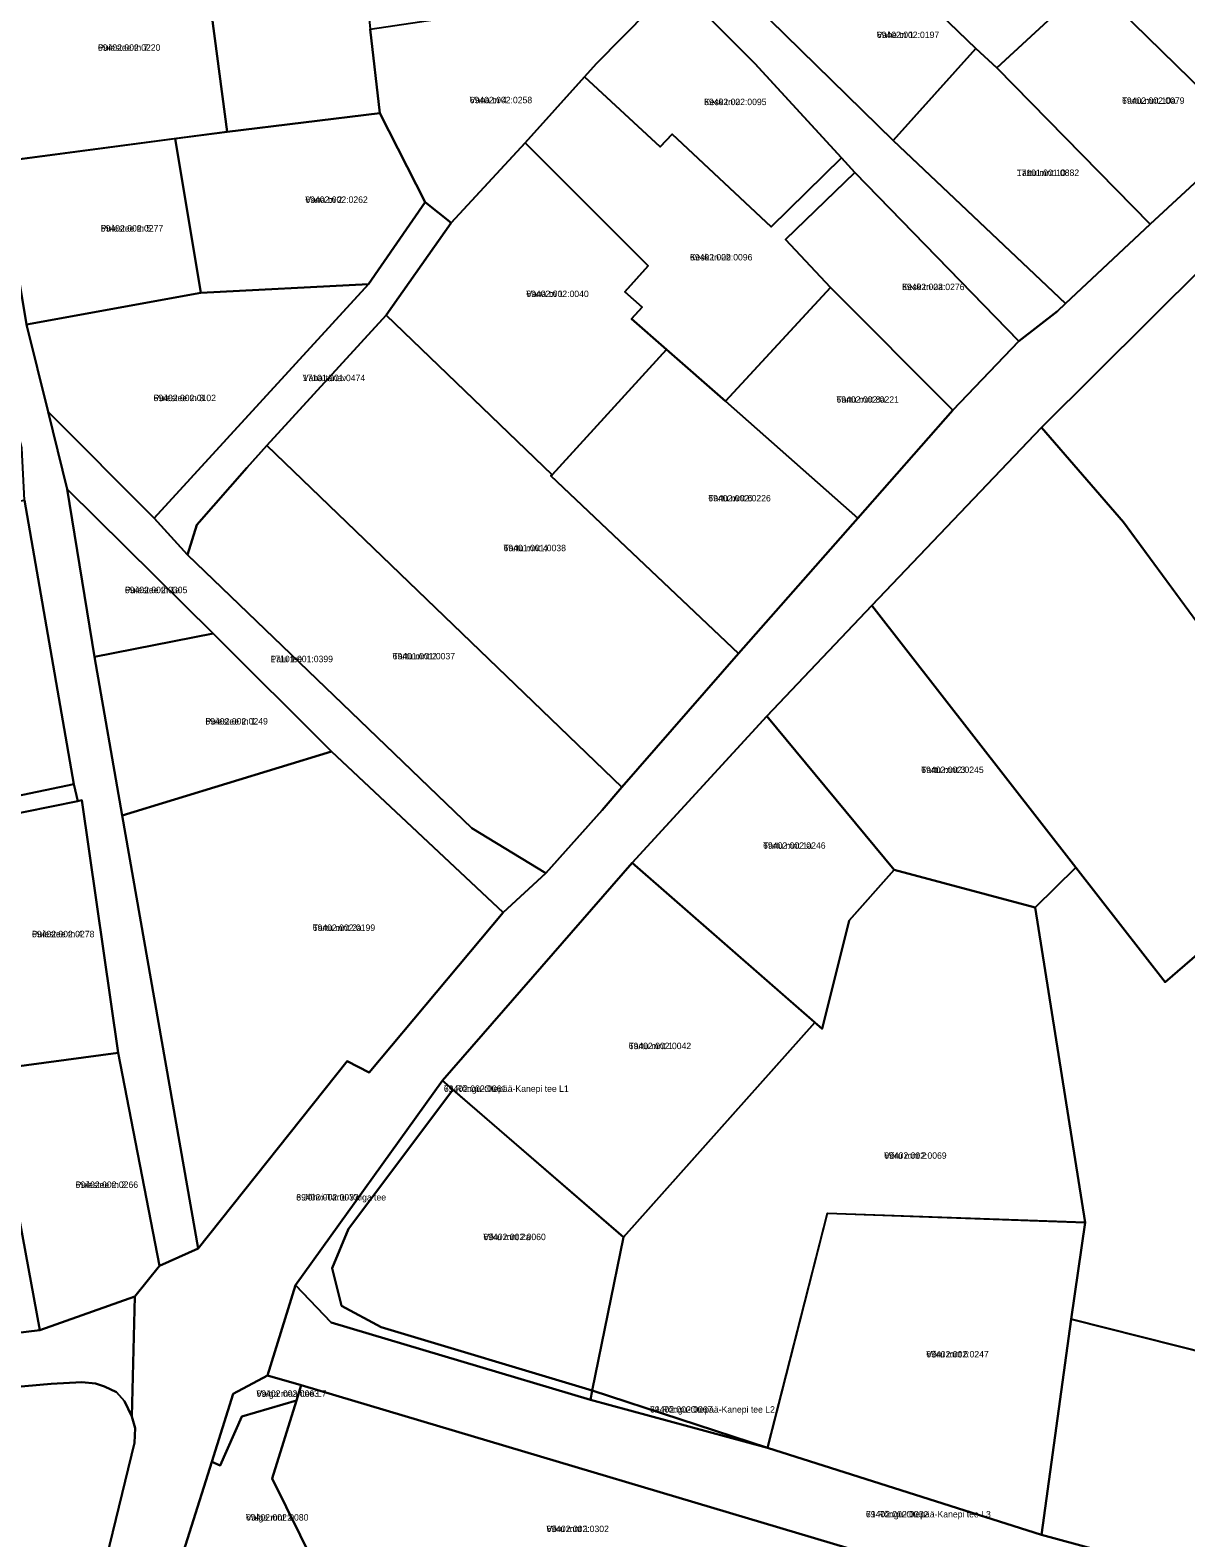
# Model space of a CAD drawing. Extents: x 621116 to 647354, y 6433782 to 6479868.
# Drawn here: x 632315.8 to 632584.2, y 6446793.4 to 6447143.7 of the extents above; entities that cross this region are included whole.
import ezdxf

# ---------------------------------------------------------------- set-up
doc = ezdxf.new("R2010")
doc.units = 0
for name, color, linetype in [('L_AADRESS', 7, 'Continuous'), ('PIIR', 7, 'Continuous'), ('TUNNUS', 7, 'Continuous')]:
    doc.layers.add(name, color=color, linetype=linetype)

msp = doc.modelspace()

# ---------------------------------------------------------------- linework, layer by layer
at = {"layer": 'PIIR'}
for points in [[(632883.55, 6447433.55), (632823.56, 6447364.54), (632765.83, 6447294.39), (632710.64, 6447218.39), (632706.33, 6447212.09), (632679.44, 6447177.2), (632680.2, 6447176.14), (632678.45, 6447175.07), (632645.86, 6447142.95), (632634.81, 6447132.1), (632588.47, 6447088.99), (632550.7, 6447051.42), (632511.3, 6447010.02), (632486.88, 6446984.32), (632455.65, 6446950.25), (632411.59, 6446899.66), (632377.44, 6446852.14), (632370.98, 6446831.17), (632362.97, 6446826.87), (632358.02, 6446811.05), (632347.63, 6446778.24)], [(633018.53, 6446892.34), (632855.22, 6446826.42), (632731.22, 6446817.27), (632630.88, 6446825.72), (632557.57, 6446844.2), (632560.82, 6446866.69), (632549.2, 6446939.86), (632558.62, 6446949.17), (632579.41, 6446922.53), (632647.93, 6446981.82), (632724.87, 6447048.64), (632767.82, 6447085.82), (632732.74, 6447116.24), (632780.64, 6447156.88), (632786.41, 6447163.78), (632792.83, 6447158.42), (632824.27, 6447148.02), (632854.81, 6447243.77), (632865.67, 6447258.13), (632870.09, 6447255.09)], [(632329.9, 6446773.82), (632340.08, 6446815.51), (632340.23, 6446818.86), (632339.46, 6446821.58), (632340.12, 6446849.46), (632345.88, 6446856.63), (632354.81, 6446860.66), (632389.48, 6446904.16), (632394.54, 6446901.51), (632425.68, 6446938.69), (632435.55, 6446947.84), (632448.65, 6446962.5), (632453.23, 6446967.82), (632480.34, 6446998.92), (632508.01, 6447030.37), (632530.09, 6447055.45), (632545.41, 6447071.48), (632554.37, 6447078.44), (632556.25, 6447080.21), (632575.88, 6447098.64), (632598.45, 6447119.53), (632620.08, 6447139.91), (632643.5, 6447161.29)], [(632300.82, 6447156.82), (632308.66, 6447113.17), (632315, 6447075.35), (632320.05, 6447055.08), (632324.42, 6447037.08), (632330.74, 6446998.15), (632337.2, 6446961.26), (632354.81, 6446860.66), (632345.88, 6446856.63), (632336.25, 6446906.14), (632327.85, 6446964.8), (632326.89, 6446964.62), (632325.97, 6446968.56), (632314.49, 6447034.52), (632313.86, 6447046.59), (632307.16, 6447073.73), (632300.78, 6447111.8), (632292.9, 6447155.68)], [(632487.56, 6447146.18), (632516.2, 6447118.12), (632556.25, 6447080.21), (632554.37, 6447078.44), (632545.41, 6447071.48), (632507.34, 6447110.67), (632504.26, 6447114.06), (632484.13, 6447135.98), (632465.58, 6447154.56)], [(632291.35, 6446838.41), (632318.09, 6446841.7), (632340.12, 6446849.46), (632339.46, 6446821.58), (632337.72, 6446825.15), (632335.87, 6446827.25), (632333.06, 6446828.6), (632331.02, 6446829.25), (632327.8, 6446829.55), (632320.73, 6446829.18), (632304.93, 6446827.8)]]:
    msp.add_lwpolyline(points, dxfattribs=at)
for points in [[(632508.36, 6447165.7), (632531.28, 6447186.21), (632562.08, 6447155.09), (632540.32, 6447135.02), (632535.43, 6447139.51)], [(632598.45, 6447119.53), (632562.08, 6447155.09), (632584.6, 6447175.85), (632620.08, 6447139.91)], [(632355.69, 6447164.73), (632392.41, 6447168.11), (632394.8, 6447144), (632397.04, 6447124.48), (632361.61, 6447120.15)], [(632516.2, 6447118.12), (632487.56, 6447146.18), (632508.36, 6447165.7), (632535.43, 6447139.51)], [(632355.69, 6447164.73), (632361.61, 6447120.15), (632308.66, 6447113.17), (632300.82, 6447156.82)], [(632598.45, 6447119.53), (632575.88, 6447098.64), (632540.32, 6447135.02), (632562.08, 6447155.09)], [(632447.32, 6447135.96), (632444.54, 6447132.89), (632430.75, 6447117.57), (632413.61, 6447098.97), (632407.57, 6447103.74), (632397.04, 6447124.48), (632394.8, 6447144), (632465.58, 6447154.56)], [(632504.26, 6447114.06), (632487.89, 6447098.08), (632464.89, 6447119.55), (632462.13, 6447116.65), (632444.54, 6447132.89), (632447.32, 6447135.96), (632465.58, 6447154.56), (632484.13, 6447135.98)], [(632516.2, 6447118.12), (632535.43, 6447139.51), (632540.32, 6447135.02), (632575.88, 6447098.64), (632556.25, 6447080.21)], [(632501.71, 6447083.97), (632477.32, 6447057.54), (632463.61, 6447069.56), (632455.47, 6447076.69), (632457.95, 6447079.4), (632453.91, 6447082.95), (632459.34, 6447088.95), (632430.75, 6447117.57), (632444.54, 6447132.89), (632462.13, 6447116.65), (632464.89, 6447119.55), (632487.89, 6447098.08), (632504.26, 6447114.06), (632507.34, 6447110.67), (632491.2, 6447095.08)], [(632394.39, 6447084.73), (632355.47, 6447082.74), (632349.47, 6447118.55), (632361.61, 6447120.15), (632397.04, 6447124.48), (632407.57, 6447103.74)], [(632349.47, 6447118.55), (632355.47, 6447082.74), (632315, 6447075.35), (632308.66, 6447113.17)], [(632430.75, 6447117.57), (632459.34, 6447088.95), (632453.91, 6447082.95), (632457.95, 6447079.4), (632455.47, 6447076.69), (632463.61, 6447069.56), (632437.02, 6447040.42), (632398.47, 6447077.52), (632413.61, 6447098.97)], [(632507.34, 6447110.67), (632545.41, 6447071.48), (632530.09, 6447055.45), (632501.71, 6447083.97), (632491.2, 6447095.08)], [(632344.64, 6447030.36), (632394.39, 6447084.73), (632407.57, 6447103.74), (632413.61, 6447098.97), (632398.47, 6447077.52), (632370.81, 6447047.22), (632366.12, 6447042.04), (632354.52, 6447028.81), (632352.33, 6447021.81)], [(632550.7, 6447051.42), (632588.47, 6447088.99), (632641.79, 6447032.42), (632621.77, 6447012.3), (632598.99, 6446989.55), (632569.7, 6447029.45)], [(632315, 6447075.35), (632355.47, 6447082.74), (632394.39, 6447084.73), (632344.64, 6447030.36), (632320.05, 6447055.08)], [(632501.71, 6447083.97), (632530.09, 6447055.45), (632508.01, 6447030.37), (632477.32, 6447057.54)], [(632436.72, 6447040.15), (632480.34, 6446998.92), (632453.23, 6446967.82), (632370.81, 6447047.22), (632398.47, 6447077.52), (632437.02, 6447040.42)], [(632463.61, 6447069.56), (632477.32, 6447057.54), (632508.01, 6447030.37), (632480.34, 6446998.92), (632436.72, 6447040.15), (632437.02, 6447040.42)], [(632320.05, 6447055.08), (632344.64, 6447030.36), (632352.33, 6447021.81), (632418.43, 6446958.33), (632435.55, 6446947.84), (632425.68, 6446938.69), (632385.82, 6446976.15), (632358.33, 6447003.54), (632324.42, 6447037.08)], [(632558.62, 6446949.17), (632511.3, 6447010.02), (632550.7, 6447051.42), (632569.7, 6447029.45), (632599.07, 6446989.55), (632621.77, 6447012.3), (632647.93, 6446981.82), (632579.41, 6446922.53)], [(632370.81, 6447047.22), (632453.23, 6446967.82), (632448.65, 6446962.5), (632435.55, 6446947.84), (632418.43, 6446958.33), (632352.33, 6447021.81), (632354.52, 6447028.81), (632366.12, 6447042.04)], [(632330.74, 6446998.15), (632324.42, 6447037.08), (632358.33, 6447003.54)], [(632314.49, 6447034.52), (632325.97, 6446968.56), (632268.52, 6446956.57), (632264.6, 6446987.12), (632259.6, 6447024.62)], [(632516.43, 6446948.67), (632486.88, 6446984.32), (632511.3, 6447010.02), (632558.62, 6446949.17), (632549.2, 6446939.86)], [(632337.2, 6446961.26), (632330.74, 6446998.15), (632358.33, 6447003.54), (632385.82, 6446976.15)], [(632499.72, 6446911.67), (632455.65, 6446950.25), (632486.88, 6446984.32), (632516.43, 6446948.67), (632505.98, 6446936.83)], [(632354.81, 6446860.66), (632337.2, 6446961.26), (632385.82, 6446976.15), (632425.68, 6446938.69), (632394.54, 6446901.51), (632389.48, 6446904.16)], [(632326.89, 6446964.62), (632296.26, 6446958.42), (632307.29, 6446899.81), (632277.79, 6446894.25), (632277.21, 6446897.8), (632272.99, 6446920.18), (632268.52, 6446956.57), (632325.97, 6446968.56)], [(632306.89, 6446902.19), (632296.26, 6446958.42), (632326.89, 6446964.62), (632327.85, 6446964.8), (632336.25, 6446906.14)], [(632498.05, 6446913.15), (632453.64, 6446863.31), (632411.59, 6446899.66), (632455.65, 6446950.25)], [(632516.43, 6446948.67), (632549.2, 6446939.86), (632560.82, 6446866.69), (632500.9, 6446868.8), (632487.04, 6446814.31), (632446.36, 6446827.67), (632453.64, 6446863.31), (632498.05, 6446913.15), (632499.72, 6446911.67), (632505.98, 6446936.83)], [(632306.89, 6446902.19), (632336.25, 6446906.14), (632345.88, 6446856.63), (632340.12, 6446849.46), (632318.09, 6446841.7), (632307.29, 6446899.81)], [(632318.09, 6446841.7), (632291.35, 6446838.41), (632275.32, 6446841.91), (632250, 6446856.81), (632216.84, 6446883.42), (632277.21, 6446897.8), (632277.79, 6446894.25), (632307.29, 6446899.81)], [(632411.59, 6446899.66), (632414.01, 6446897.51), (632389.74, 6446865.21), (632385.97, 6446856.11), (632388.12, 6446847.29), (632397.37, 6446842.35), (632446.36, 6446827.67), (632445.92, 6446825.51), (632385.73, 6446843.47), (632377.44, 6446852.14)], [(632414.01, 6446897.51), (632453.64, 6446863.31), (632446.36, 6446827.67), (632397.37, 6446842.35), (632388.12, 6446847.29), (632385.97, 6446856.11), (632389.74, 6446865.21)], [(632550.69, 6446794.14), (632487.04, 6446814.31), (632500.96, 6446868.87), (632560.82, 6446866.69), (632557.57, 6446844.2)], [(632377.44, 6446852.14), (632385.73, 6446843.47), (632445.92, 6446825.51), (632487.04, 6446814.31), (632550.69, 6446794.14), (632622.04, 6446774.77), (632669.14, 6446760.92), (632664.22, 6446744.18), (632617.18, 6446757.53), (632525.74, 6446785.08), (632378.73, 6446828.86), (632370.98, 6446831.17)], [(632550.69, 6446794.14), (632557.57, 6446844.2), (632630.88, 6446825.72), (632622.04, 6446774.77)], [(632323.13, 6446752.66), (632262.92, 6446807.33), (632252.65, 6446807.22), (632261.96, 6446821.04), (632269.25, 6446826.22), (632272.4, 6446828.44), (632273.3, 6446828.95), (632276.23, 6446828.92), (632288.42, 6446827.75), (632295.46, 6446827.42), (632304.93, 6446827.8), (632320.73, 6446829.18), (632327.8, 6446829.55), (632331.02, 6446829.25), (632333.06, 6446828.6), (632335.87, 6446827.25), (632337.72, 6446825.15), (632339.46, 6446821.58), (632340.23, 6446818.86), (632340.08, 6446815.51), (632329.9, 6446773.82)], [(632378.73, 6446828.86), (632377.66, 6446825.3), (632364.96, 6446821.59), (632359.95, 6446810.25), (632358.02, 6446811.05), (632362.97, 6446826.87), (632370.98, 6446831.17)], [(632525.96, 6446778.3), (632522.31, 6446760.65), (632460.03, 6446772.96), (632418.66, 6446780.63), (632384.27, 6446787.02), (632381.79, 6446787.46), (632372.05, 6446807.23), (632377.66, 6446825.3), (632378.73, 6446828.86), (632525.74, 6446785.08)], [(632445.92, 6446825.51), (632446.36, 6446827.67), (632487.04, 6446814.31)], [(632377.66, 6446825.3), (632372.05, 6446807.23), (632381.79, 6446787.46), (632384.27, 6446787.02), (632379.03, 6446769.18), (632347.63, 6446778.24), (632358.02, 6446811.05), (632359.95, 6446810.25), (632364.96, 6446821.59)]]:
    msp.add_lwpolyline(points, close=True, dxfattribs=at)

# ---------------------------------------------------------------- texts
at = {"layer": 'L_AADRESS'}
for s, p in [('Vahe tn 1', (632512.43, 6447141.91)), ('Puiestee tn 7', (632331.57, 6447138.95)), ('Vana tn 4', (632417.9, 6447126.76)), ('Kesk tn 2', (632472.33, 6447126.32)), ('Tartu mnt 10a', (632569.39, 6447126.62)), ('Tartu mnt 10', (632544.92, 6447109.86)), ('Vana tn 2', (632379.73, 6447103.61)), ('Puiestee tn 5', (632332.23, 6447096.95)), ('Kesk tn 2b', (632469.05, 6447090.23)), ('Vana tn 1', (632431.04, 6447081.73)), ('Kesk tn 2a', (632518.3, 6447083.34)), ('Vana tänav', (632379.12, 6447062.19)), ('Puiestee tn 3', (632344.48, 6447057.54)), ('Tartu mnt 8a', (632503.06, 6447057.17)), ('Tartu mnt 6', (632473.31, 6447034.24)), ('Tartu mnt 4', (632425.75, 6447022.67)), ('Puiestee tn 1a', (632337.83, 6447012.92)), ('Palu tee', (632371.65, 6446996.88)), ('Tartu mnt 2', (632400, 6446997.53)), ('Puiestee tn 1', (632356.52, 6446982.4)), ('Tartu mnt 3', (632522.75, 6446971.13)), ('Tartu mnt 1a', (632486.04, 6446953.52)), ('Puiestee tn 4', (632316.25, 6446932.96)), ('Tartu mnt 2a', (632381.44, 6446934.44)), ('Tartu mnt 1', (632454.82, 6446906.97)), ('71 Rõngu-Otepää-Kanepi tee L1', (632411.9, 6446897.04)), ('Võru mnt 2', (632514.15, 6446881.49)), ('Puiestee tn 2', (632326.39, 6446874.72)), ('3 Jõhvi-Tartu-Valga tee', (632377.63, 6446871.8)), ('Võru mnt 2a', (632421.07, 6446862.59)), ('Võru mnt 6', (632523.93, 6446835.33)), ('Valga maantee L7', (632368.38, 6446826.18)), ('71 Rõngu-Otepää-Kanepi tee L2', (632459.77, 6446822.5)), ('Valga mnt 2', (632365.95, 6446797.42)), ('71 Rõngu-Otepää-Kanepi tee L3', (632509.91, 6446798.16)), ('Võru mnt 1', (632435.72, 6446794.75))]:
    msp.add_text(s, height=1.5, dxfattribs=at).set_placement(p)
at = {"layer": 'TUNNUS'}
for s, p in [('69402:002:0197', (632512.43, 6447141.91)), ('69402:002:0220', (632331.57, 6447138.95)), ('69402:002:0258', (632417.9, 6447126.76)), ('69402:002:0095', (632472.33, 6447126.32)), ('69402:002:0079', (632569.39, 6447126.62)), ('17101:001:0882', (632544.92, 6447109.86)), ('69402:002:0262', (632379.73, 6447103.61)), ('69402:002:0277', (632332.23, 6447096.95)), ('69402:002:0096', (632469.05, 6447090.23)), ('69402:002:0040', (632431.04, 6447081.73)), ('69402:002:0276', (632518.3, 6447083.34)), ('17101:001:0474', (632379.12, 6447062.19)), ('69402:002:0102', (632344.48, 6447057.54)), ('69402:002:0221', (632503.06, 6447057.17)), ('69402:002:0226', (632473.31, 6447034.24)), ('69401:001:0038', (632425.75, 6447022.67)), ('69402:002:0305', (632337.83, 6447012.92)), ('17101:001:0399', (632371.65, 6446996.88)), ('69401:001:0037', (632400, 6446997.53)), ('69402:002:0249', (632356.52, 6446982.4)), ('69402:002:0245', (632522.75, 6446971.13)), ('69402:002:0246', (632486.04, 6446953.52)), ('69402:002:0278', (632316.25, 6446932.96)), ('69402:002:0199', (632381.44, 6446934.44)), ('69402:002:0042', (632454.82, 6446906.97)), ('69402:002:0061', (632411.9, 6446897.04)), ('69402:002:0069', (632514.15, 6446881.49)), ('69402:002:0266', (632326.39, 6446874.72)), ('69402:002:0033', (632377.63, 6446871.8)), ('69402:002:0060', (632421.07, 6446862.59)), ('69402:002:0247', (632523.93, 6446835.33)), ('69402:002:0063', (632368.38, 6446826.18)), ('69402:002:0067', (632459.77, 6446822.5)), ('69402:002:0080', (632365.95, 6446797.42)), ('69402:002:0032', (632509.91, 6446798.16)), ('69402:002:0302', (632435.72, 6446794.75))]:
    msp.add_text(s, height=1.5, dxfattribs=at).set_placement(p)

doc.saveas('drawing.dxf')
